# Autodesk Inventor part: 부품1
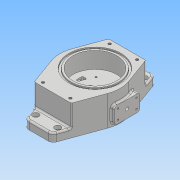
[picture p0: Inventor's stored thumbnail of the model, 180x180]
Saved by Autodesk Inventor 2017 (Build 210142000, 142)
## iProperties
Part Number: 부품1
Material: 일반
Document SubType Name: Modeling
Designer: MRC
Density: 1 g/cm^3
Appearance: 기본값
Mass: 580.887 g
Surface Area: 721.394 cm^2
Volume: 580.887 cm^3
Author: MRC
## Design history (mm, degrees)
sketch "스케치1"
  geometry: L1 (0, 94)-(0, -94); L2 (0, 94)-(-17.315, 94); L3 (-26.711, 87.42)-(-51.683, 18.811); L4 (0, 0)-(-90.532, 0); L5 (0, -94)-(-17.315, -94); L6 (-26.711, -87.42)-(-51.683, -18.811); L7 (26.711, 87.42)-(51.683, 18.811); L8 (26.711, -87.42)-(51.683, -18.811); L9 (0, 68)-(0, -68); L10 (-33.78, 68)-(33.78, 68); L11 (-33.78, -68)-(33.78, -68); L12 (0, 94)-(17.315, 94); L13 (0, -94)-(17.315, -94); A1 r 10 centre (-17.315, 84) between (-17.315, 94) and (-26.711, 87.42); A2 r 10 centre (-17.315, -84) between (-26.711, -87.42) and (-17.315, -94); A3 r 10 centre (17.315, 84) between (26.711, 87.42) and (17.315, 94); A4 r 10 centre (17.315, -84) between (17.315, -94) and (26.711, -87.42); A5 r 55 centre (0, 0) between (51.683, -18.811) and (51.683, 18.811); A6 r 55 centre (0, 0) between (-51.683, 18.811) and (-51.683, -18.811); 1 further point
  constraints: 26 end point, 12 point on circle, 12 symmetric about line, 6 centre point, 6 point on line, 4 horizontal, 4 midpoint, 3 tangent, 2 coincident, 1 vertical, 3 other
  dimensions: "d1" = 188 distance of L1.start L1.end; "d2" = 20 deg angle of L1 L3; "d3" = 10 radius of A1; "d4" = 136 distance of L9.start L9.end; "d5" = 55 radius of A6
extrude "돌출1" new body sketch "스케치1" distance "d6" = 15; taper "d7" = 0 deg
extrude "돌출2" join sketch "스케치1" distance "d8" = 55; taper "d9" = 0 deg
sketch "스케치3"
  geometry: C1 r 17.5 at (0, 0); A1 r 55 centre (0, 0) between (-51.683, 18.811) and (-51.683, -18.811) reference
  constraints: 1 centre point, 1 coincident
  dimensions: "d10" = 35 diameter of C1
extrude "돌출3" join sketch "스케치3" distance "d11" = 5; taper "d12" = 0 deg
fillet "모깎기1" dims "d13" = 1
node "작업 평면2"
sketch "스케치8"
  geometry: L1 (9, 35)-(-27, 35); L2 (-32, 30)-(-32, 10); L3 (-27, 5)-(9, 5); L4 (14, 10)-(14, 30); L5 (14, 35)-(-32, 5); L6 (-32, 35)-(14, 5); C1 r 3 at (-9, 20); A1 r 5 centre (-27, 10) between (-32, 10) and (-27, 5); A2 r 5 centre (9, 10) between (9, 5) and (14, 10); A3 r 5 centre (9, 30) between (14, 30) and (9, 35); A4 r 5 centre (-27, 30) between (-27, 35) and (-32, 30); 1 further point
  constraints: 12 end point, 8 point on circle, 8 point on line, 8 tangent, 5 centre point, 3 equal radius, 2 midpoint, 2 parallel, 1 horizontal, 1 perpendicular
  dimensions: "d38" = 6 diameter of C1; "d39" = 9 horizontal distance of C1.centre point (0, 0); "d40" = 20 vertical distance of C1.centre point (0, 0); "d41" = 46 distance of L6.end L5.end; "d42" = 30 distance of L5.end L6.start; "d43" = 5 radius of A1 (derived)
extrude "돌출5" join sketch "스케치8" distance "d44" = 118; taper "d45" = 0 deg
sketch "스케치4"
  geometry: L1 (51.683, 18.811)-(33.78, 68) reference; L2 (-33.78, 68)-(33.78, 68) reference; L3 (33.78, 68)-(51.683, 18.811) reference; L4 (51.683, -18.811)-(33.78, -68) reference; L5 (33.78, -68)-(-33.78, -68) reference; L6 (-33.78, -68)-(-51.683, -18.811) reference; L7 (-51.683, 18.811)-(-33.78, 68) reference; C1 r 40 at (0, -9); A1 r 55 centre (0, 0) between (51.683, -18.811) and (51.683, 18.811) reference; A2 r 55 centre (0, 0) between (51.683, -18.811) and (51.683, 18.811) reference; A3 r 55 centre (0, 0) between (-51.683, 18.811) and (-51.683, -18.811) reference
  constraints: 1 centre point
  dimensions: "d73" = 80 diameter of C1; "d74" = 9 distance of A1.centre C1.centre; "d75" = 58.07818 distance from line of C1.centre L1
extrude "돌출4" cut sketch "스케치4" distance "d15" = 30; taper "d16" = 0 deg
sketch "스케치9"
  geometry: C1 r 3 at (-20, -9) reference; 5 further points
  dimensions: "d48" = 9 horizontal distance of C1.centre point (-29, -26); "d49" = 18 distance of point (-11, -26) point (-29, -26); "d50" = 17 vertical distance of C1.centre point (-29, -26); "d51" = 34 distance of point (-29, 8) point (-29, -26); "d52" = 9 horizontal distance of C1.centre point (-29, 8); "d53" = 18 distance of point (-11, 8) point (-29, 8); "d54" = 17 vertical distance of point (-11, 8) C1.centre; "d55" = 34 distance of point (-11, -26) point (-11, 8)
hole "구멍3" sketch "스케치9" at (-29, -26), (-11, -26), (-11, 8), (-29, 8) diameter "d56" = 3.242; stored, may be unused: countersink angle "d60" = 90 deg, drill point angle "d62" = 118 deg; dims "d57" = 8, "d58" = 20, "d59" = 10, "d61" = 10
sketch "스케치11"
  geometry: L1 (-33.78, 68)-(33.78, 68) reference; L2 (33.78, 68)-(51.683, 18.811) reference; L3 (51.683, -18.811)-(33.78, -68) reference; L4 (33.78, -68)-(-33.78, -68) reference; L5 (-33.78, -68)-(-51.683, -18.811) reference; L6 (-51.683, 18.811)-(-33.78, 68) reference; L7 (-33.78, 68)-(33.78, 68) reference; L8 (33.78, 68)-(51.683, 18.811) reference; L9 (51.683, -18.811)-(33.78, -68) reference; L10 (33.78, -68)-(-33.78, -68) reference; L11 (-33.78, -68)-(-51.683, -18.811) reference; L12 (-51.683, 18.811)-(-33.78, 68) reference; C1 r 40 at (0, -9) reference; C2 r 40 at (0, -9) reference; C3 r 40 at (0, -9) reference; C4 r 47.5 at (0, -9); C5 r 43.4 at (0, -9); A1 r 55 centre (0, 0) between (51.683, -18.811) and (51.683, 18.811) reference; A2 r 55 centre (0, 0) between (-51.683, 18.811) and (-51.683, -18.811) reference; A3 r 55 centre (0, 0) between (51.683, -18.811) and (51.683, 18.811) reference; A4 r 55 centre (0, 0) between (-51.683, 18.811) and (-51.683, -18.811) reference
  constraints: 2 centre point, 1 coincident
  dimensions: "d76" = 95 diameter of C4; "d77" = 4.1 radial gap between concentric circles of C4 C5
extrude "돌출8" cut sketch "스케치11" distance "d78" = 2.4; taper "d79" = 0 deg
fillet "모깎기3" dims "d80" = 0.5
sketch "스케치13"
  geometry: 1 further point
hole "구멍4" sketch "스케치13" at (0, 9) diameter "d81" = 16; stored, may be unused: countersink angle "d85" = 90 deg, drill point angle "d87" = 118 deg; dims "d82" = 8, "d83" = 20, "d84" = 10, "d86" = 10
sketch "스케치15"
  geometry: C1 r 40 at (0, 0) reference; 2 further points
  dimensions: "d95" = 30 distance of point (15, -17) point (-15, -17); "d96" = 15 horizontal distance of C1.centre point (15, -17); "d97" = 17 vertical distance of C1.centre point (15, -17); "d98" = 17 vertical distance of C1.centre point (-15, -17)
hole "구멍6" sketch "스케치15" at (15, -17), (-15, -17) diameter "d99" = 3.242; stored, may be unused: countersink angle "d103" = 90 deg, drill point angle "d105" = 118 deg; dims "d100" = 8, "d101" = 20, "d102" = 10, "d104" = 10
sketch "스케치16"
  geometry: L1 (-33.78, 77)-(33.78, 77) reference; L2 (33.78, 77)-(51.683, 27.811) reference; L3 (53.188, 23)-(59, 23) reference; L4 (59, 23)-(59, -23) reference; L5 (59, -23)-(46.883, -23) reference; L6 (46.883, -23)-(33.78, -59) reference; L7 (33.78, -59)-(-33.78, -59) reference; L8 (-33.78, -59)-(-46.883, -23) reference; L9 (-46.883, -23)-(-59, -23) reference; L10 (-59, -23)-(-59, 23) reference; L11 (-59, 23)-(-53.188, 23) reference; L12 (-51.683, 27.811)-(-33.78, 77) reference; L13 (-22.517, -6)-(-26.702, -6); L14 (-26.702, 6)-(-25.515, 6); L15 (0, 9)-(0, -73.922); L16 (22.517, -6)-(26.702, -6); L17 (26.702, 6)-(25.515, 6); C1 r 40 at (0, 0) reference; C2 r 1.621 at (15, -17) reference; C3 r 1.621 at (-15, -17) reference; C4 r 10 at (0, 9) reference; C5 r 40 at (0, 0) reference; A1 r 55 centre (0, 9) between (53.188, 23) and (51.683, 27.811) reference; A2 r 55 centre (0, 9) between (-51.683, 27.811) and (-53.188, 23) reference; A3 r 24 centre (0, 9) between (-23.552, 4.385) and (-20.785, -3); A4 r 29 centre (0, 0) between (-28.68, 4.296) and (-28.68, -4.296); A5 r 2 centre (-26.702, -4) between (-28.68, -4.296) and (-26.702, -6); A6 r 2 centre (-22.517, -4) between (-22.517, -6) and (-20.785, -3); A7 r 2 centre (-25.515, 4) between (-23.552, 4.385) and (-25.515, 6); A8 r 2 centre (-26.702, 4) between (-26.702, 6) and (-28.68, 4.296); A9 r 24 centre (0, 9) between (20.785, -3) and (23.552, 4.385); A10 r 2 centre (22.517, -4) between (20.785, -3) and (22.517, -6); A11 r 2 centre (26.702, -4) between (26.702, -6) and (28.68, -4.296); A12 r 29 centre (0, 0) between (28.68, -4.296) and (28.68, 4.296); A13 r 2 centre (25.515, 4) between (25.515, 6) and (23.552, 4.385); A14 r 2 centre (26.702, 4) between (28.68, 4.296) and (26.702, 6); 5 further points
  constraints: 28 point on circle, 12 centre point, 12 symmetric about line, 10 end point, 8 tangent, 4 point on line, 3 equal radius, 2 coincident, 1 horizontal, 1 horizontal alignment, 1 parallel, 1 vertical, 6 other
  dimensions: "d108" = 12 distance of point (-28.373, -6) point (-28.373, 6); "d109" = 2 radius of A5; "d110" = 24 radius of A3; "d111" = 29 radius of A4; "d112" = 17 distance between parallel lines of L5 L13; "d113" = 77.73499 distance from line of point (-18.735, 0) L4
extrude "돌출9" cut sketch "스케치16" distance "d114" = 12; taper "d115" = 0 deg
extrude "돌출10" cut sketch "스케치8" stored distance "d116" = 12; taper "d117" = 0 deg
sketch "스케치17"
  geometry: C1 r 3 at (20, -9) reference; C2 r 3 at (20, -9); 1 further point
  constraints: 1 centre point, 1 coincident, 1 concentric
extrude "돌출11" cut sketch "스케치17" stored distance "d118" = 12; taper "d119" = 0 deg
sketch "스케치18"
  geometry: L1 (-17.5, -4)-(-17.5, 0) reference; L2 (-17.5, 0)-(-94, 0) reference; L3 (-94, 0)-(-94, 15) reference; L4 (-94, 15)-(-68, 15) reference; L5 (-68, 15)-(-68, 55) reference; L6 (-68, 55)-(-56.5, 55) reference; L7 (-56.5, 55)-(-56.5, 53.1) reference; L8 (-56, 52.6)-(-52.9, 52.6) reference; L9 (-52.4, 53.1)-(-52.4, 55) reference; L10 (-52.4, 55)-(-49, 55) reference; L11 (-49, 55)-(-49, 25) reference; L12 (-49, 25)-(-10, 25) reference; L13 (-10, 25)-(-10, 15) reference; L14 (-10, 15)-(-8, 15) reference; L15 (-8, 15)-(-8, -5) reference; L16 (-8, -5)-(-16.5, -5) reference; L17 (16.5, -5)-(8, -5) reference; L18 (8, -5)-(8, 15) reference; L19 (8, 15)-(10, 15) reference; L20 (10, 15)-(10, 25) reference; L21 (10, 25)-(31, 25) reference; L22 (31, 25)-(31, 55) reference; L23 (31, 55)-(34.4, 55) reference; L24 (34.4, 55)-(34.4, 53.1) reference; L25 (34.9, 52.6)-(38, 52.6) reference; L26 (38.5, 53.1)-(38.5, 55) reference; L27 (38.5, 55)-(68, 55) reference; L28 (68, 55)-(68, 15) reference; L29 (68, 15)-(94, 15) reference; L30 (94, 15)-(94, 0) reference; L31 (94, 0)-(17.5, 0) reference; L32 (17.5, 0)-(17.5, -4) reference; L33 (18.811, 0)-(-18.811, 0) reference; L34 (16.5, -5)-(-16.5, -5) reference; L35 (-12.731, -5)-(0, -5); L36 (0, -5)-(0, 3.4); L37 (0, 3.4)-(-12.3, 3.4); L38 (-12.5, 3.2)-(-12.5, -4.6); L39 (-12.5, -4.6)-(-12.731, -5); A1 r 1 centre (-16.5, -4) between (-17.5, -4) and (-16.5, -5) reference; A2 r 0.5 centre (-56, 53.1) between (-56.5, 53.1) and (-56, 52.6) reference; A3 r 0.5 centre (-52.9, 53.1) between (-52.9, 52.6) and (-52.4, 53.1) reference; A4 r 1 centre (16.5, -4) between (16.5, -5) and (17.5, -4) reference; A5 r 0.5 centre (34.9, 53.1) between (34.4, 53.1) and (34.9, 52.6) reference; A6 r 0.5 centre (38, 53.1) between (38, 52.6) and (38.5, 53.1) reference; A7 r 0.2 centre (-12.3, 3.2) between (-12.3, 3.4) and (-12.5, 3.2); 1 further point
  constraints: 10 end point, 2 point on circle, 2 tangent, 2 vertical, 1 centre point, 1 horizontal, 1 midpoint, 1 point on line
  dimensions: "d166" = 8.4 distance of L35.end L36.end; "d167" = 0.4 vertical distance of L35.start L38.end; "d168" = 30 deg angle of L38 L39; "d169" = 0.2 radius of A7 (derived); "d170" = 106.5 distance between parallel lines of L30 L38
  node "절단 모서리 투영5"
sketch "스케치19"
  geometry: A1 r 55 centre (0, 0) between (51.683, -18.811) and (51.683, 18.811) reference; 4 further points
  dimensions: "d127" = 122 distance of point (25, -61) point (25, 61); "d128" = 61 vertical distance of A1.centre point (25, 61); "d129" = 61 vertical distance of A1.centre point (-25, 61); "d130" = 122 distance of point (-25, -61) point (-25, 61); "d131" = 50 distance of point (-25, -61) point (25, -61); "d132" = 25 horizontal distance of A1.centre point (25, -61); "d133" = 25 horizontal distance of A1.centre point (25, 61); "d134" = 25 horizontal distance of A1.centre point (-25, 61)
hole "구멍7" sketch "스케치19" at (25, 61), (-25, 61), (-25, -61), (25, -61) diameter "d135" = 4.917; stored, may be unused: countersink angle "d139" = 90 deg, drill point angle "d141" = 118 deg; dims "d136" = 12, "d137" = 20, "d138" = 10, "d140" = 14
sketch "스케치20"
  geometry: L1 (-26.702, -15)-(-22.517, -15) reference; L2 (-25.515, -3)-(-26.702, -3) reference; L3 (26.702, -3)-(25.515, -3) reference; L4 (22.517, -15)-(26.702, -15) reference; L5 (26.711, 87.42)-(33.78, 68) reference; L6 (-51.683, 18.811)-(-33.78, 68) reference; L7 (-59, 14)-(-53.188, 14) reference; L8 (-59, -32)-(-59, 14) reference; L9 (-46.883, -32)-(-59, -32) reference; L10 (-33.78, -68)-(-46.883, -32) reference; L11 (33.78, -68)-(26.711, -87.42) reference; L12 (17.315, -94)-(-17.315, -94) reference; L13 (-26.711, -87.42)-(-33.78, -68) reference; L14 (-17.315, 94)-(17.315, 94) reference; L15 (-33.78, 68)-(-26.711, 87.42) reference; L16 (33.78, 68)-(51.683, 18.811) reference; L17 (53.188, 14)-(59, 14) reference; L18 (59, 14)-(59, -32) reference; L19 (59, -32)-(46.883, -32) reference; L20 (46.883, -32)-(33.78, -68) reference; L21 (-33.78, 68)-(33.78, 68) reference; L22 (33.78, -68)-(-33.78, -68) reference; C1 r 1.621 at (15, -26) reference; C2 r 1.621 at (-15, -26) reference; C3 r 10 at (0, 0) reference; C4 r 8 at (0, 0) reference; A1 r 2 centre (-22.517, -13) between (-22.517, -15) and (-20.785, -12) reference; A2 r 24 centre (0, 0) between (-23.552, -4.615) and (-20.785, -12) reference; A3 r 2 centre (-25.515, -5) between (-23.552, -4.615) and (-25.515, -3) reference; A4 r 2 centre (-26.702, -5) between (-26.702, -3) and (-28.68, -4.704) reference; A5 r 29 centre (0, -9) between (-28.68, -4.704) and (-28.68, -13.296) reference; A6 r 2 centre (-26.702, -13) between (-28.68, -13.296) and (-26.702, -15) reference; A7 r 2 centre (26.702, -13) between (26.702, -15) and (28.68, -13.296) reference; A8 r 29 centre (0, -9) between (28.68, -13.296) and (28.68, -4.704) reference; A9 r 2 centre (26.702, -5) between (28.68, -4.704) and (26.702, -3) reference; A10 r 2 centre (25.515, -5) between (25.515, -3) and (23.552, -4.615) reference; A11 r 24 centre (0, 0) between (20.785, -12) and (23.552, -4.615) reference; A12 r 2 centre (22.517, -13) between (20.785, -12) and (22.517, -15) reference; A13 r 10 centre (17.315, 84) between (26.711, 87.42) and (17.315, 94) reference; A14 r 55 centre (0, 0) between (-51.683, 18.811) and (-53.188, 14) reference; A15 r 10 centre (17.315, -84) between (17.315, -94) and (26.711, -87.42) reference; A16 r 10 centre (-17.315, -84) between (-26.711, -87.42) and (-17.315, -94) reference; A17 r 10 centre (-17.315, 84) between (-17.315, 94) and (-26.711, 87.42) reference; A18 r 55 centre (0, 0) between (53.188, 14) and (51.683, 18.811) reference; 5 further points
  dimensions: "d142" = 20 horizontal distance of point (0, 0) point (-20, -79); "d143" = 40 distance of point (20, -79) point (-20, -79); "d144" = 158 distance of point (-20, 79) point (-20, -79); "d146" = 79 vertical distance of point (0, 0) point (-20, -79); "d147" = 79 vertical distance of A2.centre point (20, 79); "d148" = 158 distance of point (20, -79) point (20, 79); "d149" = 40 distance of point (20, 79) point (-20, 79); "d150" = 20 horizontal distance of point (0, 0) point (20, 79)
hole "구멍8" sketch "스케치20" at (-20, -79), (20, -79), (-20, 79), (20, 79) diameter "d151" = 6.6; stored, may be unused: countersink angle "d155" = 90 deg, drill point angle "d157" = 118 deg; dims "d152" = 12, "d153" = 11, "d154" = 6.6, "d156" = 14
fillet "모깎기5" dims "d158" = 3
fillet "모깎기6" dims "d159" = 3
sketch "스케치21"
  geometry: L1 (0, 37)-(63.358, 37) reference; L2 (53.868, 16.021)-(9.49, 16.021); L3 (9.49, 16.021)-(9.49, 27.979); L4 (9.49, 27.979)-(53.868, 27.979); L5 (53.868, 27.979)-(53.868, 16.021); L6 (9.49, 22)-(53.868, 22); L7 (31.679, 16.021)-(31.679, 27.979); L8 (14.365, -18)-(48.994, -18) reference; 3 further points
  constraints: 6 midpoint, 4 end point, 1 vertical alignment, 2 other
  dimensions: "d160" = 15 distance between parallel lines of L1 L6
feature "엠보싱1" sketch "스케치21" dims "d1" = 188, "d2" = 20 deg, "d3" = 10, "d4" = 136, "d5" = 55, "d161" = 0.5, "d162" = 0
fillet "모깎기7" dims "d163" = 2
revolve "회전2" stored, may be unused: angle "d171" = 90 deg
node "솔리드1"
mirror "미러1"
node "절단 모서리 투영1"
node "절단 모서리 투영2"
node "절단 모서리 투영3"
node "절단 모서리 투영4"
node "절단 모서리 투영6"
other parameters: "d37" = 59, "d106" = 48, "d107" = 58
